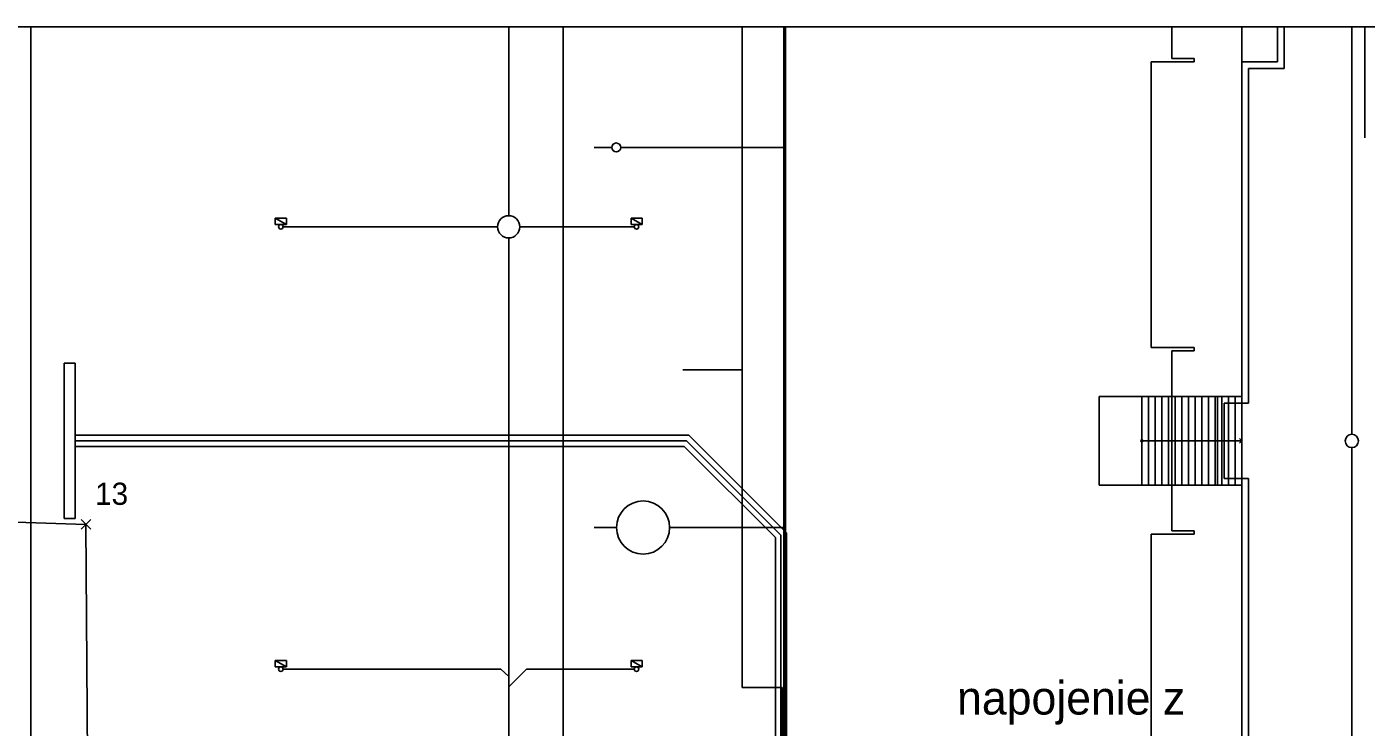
# Model space of a CAD drawing. Extents: x -263993 to -263783, y -1242294 to -1242146.
# Drawn here: x -263948.3 to -263888, y -1242177.3 to -1242145.8 of the extents above; entities that cross this region are included whole.
import ezdxf

# ---------------------------------------------------------------- set-up
doc = ezdxf.new("R2010")
doc.units = 0
for name, color, linetype in [('KFA_2D_SITUACIA_DSP', 7, 'Continuous'), ('KFA_ROZVODY_NN_BODY', 7, 'Continuous'), ('KFA_ROZVODY_NN_TRASA', 7, 'Continuous'), ('POPIS', 7, 'Continuous'), ('RAM_NA_TLAC_A3_1-500', 7, 'Continuous')]:
    doc.layers.add(name, color=color, linetype=linetype)

msp = doc.modelspace()

# ---------------------------------------------------------------- linework, layer by layer
at = {"layer": 'KFA_2D_SITUACIA_DSP'}
for p, q in [((-263948.093, -1242145.754), (-263948.093, -1242241.458)), ((-263926.593, -1242145.754), (-263926.593, -1242154.252)), ((-263926.593, -1242145.754), (-263926.593, -1242154.252)), ((-263924.143, -1242145.754), (-263924.143, -1242185.14)), ((-263916.093, -1242145.754), (-263916.093, -1242175.482)), ((-263914.218, -1242196.332), (-263914.218, -1242145.754)), ((-263914.143, -1242196.333), (-263914.143, -1242145.754)), ((-263896.768, -1242145.754), (-263896.768, -1242147.182)), ((-263893.618, -1242162.382), (-263893.618, -1242145.754)), ((-263892.018, -1242147.332), (-263892.018, -1242145.754)), ((-263892.018, -1242145.754), (-263892.018, -1242147.332)), ((-263891.718, -1242145.754), (-263891.718, -1242147.632)), ((-263888.673, -1242145.754), (-263888.673, -1242164.087)), ((-263895.768, -1242147.332), (-263897.693, -1242147.332)), ((-263897.693, -1242147.332), (-263897.693, -1242160.182)), ((-263896.768, -1242147.182), (-263895.768, -1242147.182)), ((-263895.768, -1242147.182), (-263895.768, -1242147.332)), ((-263893.618, -1242181.432), (-263893.618, -1242147.332)), ((-263893.618, -1242147.332), (-263892.018, -1242147.332)), ((-263892.018, -1242147.332), (-263893.618, -1242147.332)), ((-263893.618, -1242147.332), (-263893.618, -1242162.382)), ((-263891.718, -1242147.632), (-263893.318, -1242147.632)), ((-263893.318, -1242147.632), (-263893.318, -1242162.682)), ((-263921.957, -1242151.182), (-263922.757, -1242151.182)), ((-263917.093, -1242151.182), (-263921.557, -1242151.182)), ((-263914.143, -1242151.182), (-263917.093, -1242151.182)), ((-263937.093, -1242154.652), (-263937.093, -1242154.362)), ((-263937.093, -1242154.362), (-263936.593, -1242154.362)), ((-263936.593, -1242154.652), (-263937.093, -1242154.362)), ((-263936.593, -1242154.652), (-263937.093, -1242154.362)), ((-263937.093, -1242154.362), (-263937.093, -1242154.652)), ((-263936.593, -1242154.362), (-263936.593, -1242154.652)), ((-263921.093, -1242154.652), (-263921.093, -1242154.362)), ((-263921.093, -1242154.362), (-263920.593, -1242154.362)), ((-263920.593, -1242154.652), (-263921.093, -1242154.362)), ((-263920.593, -1242154.652), (-263921.093, -1242154.362)), ((-263921.093, -1242154.362), (-263921.093, -1242154.652)), ((-263920.593, -1242154.362), (-263920.593, -1242154.652)), ((-263936.593, -1242154.652), (-263937.093, -1242154.652)), ((-263937.093, -1242154.652), (-263936.593, -1242154.652)), ((-263936.743, -1242154.752), (-263927.093, -1242154.752)), ((-263920.944, -1242154.752), (-263926.093, -1242154.752)), ((-263920.593, -1242154.652), (-263921.093, -1242154.652)), ((-263921.093, -1242154.652), (-263920.593, -1242154.652)), ((-263926.593, -1242155.252), (-263926.593, -1242204.252)), ((-263897.693, -1242160.182), (-263895.768, -1242160.182)), ((-263895.768, -1242160.332), (-263896.768, -1242160.332)), ((-263896.768, -1242160.332), (-263896.768, -1242168.432)), ((-263895.768, -1242160.182), (-263895.768, -1242160.332)), ((-263946.093, -1242160.882), (-263946.593, -1242160.882)), ((-263946.593, -1242160.882), (-263946.593, -1242167.882)), ((-263946.093, -1242167.882), (-263946.093, -1242160.882)), ((-263916.093, -1242161.182), (-263918.763, -1242161.182)), ((-263900.043, -1242166.382), (-263900.043, -1242162.382)), ((-263900.043, -1242162.382), (-263893.618, -1242162.382)), ((-263898.118, -1242162.382), (-263898.118, -1242166.382)), ((-263897.818, -1242162.382), (-263897.818, -1242166.382)), ((-263897.518, -1242162.382), (-263897.518, -1242166.382)), ((-263897.218, -1242162.382), (-263897.218, -1242166.382)), ((-263896.918, -1242162.382), (-263896.918, -1242166.382)), ((-263896.618, -1242162.382), (-263896.618, -1242166.382)), ((-263896.318, -1242162.382), (-263896.318, -1242166.382)), ((-263896.018, -1242162.382), (-263896.018, -1242166.382)), ((-263895.718, -1242162.382), (-263895.718, -1242166.382)), ((-263895.418, -1242162.382), (-263895.418, -1242166.382)), ((-263895.118, -1242162.382), (-263895.118, -1242166.382)), ((-263894.818, -1242162.382), (-263894.818, -1242166.382)), ((-263893.618, -1242162.382), (-263894.718, -1242162.382)), ((-263894.718, -1242162.382), (-263894.718, -1242166.382)), ((-263894.518, -1242162.382), (-263894.518, -1242166.382)), ((-263894.218, -1242162.382), (-263894.218, -1242166.382)), ((-263893.918, -1242162.382), (-263893.918, -1242166.382)), ((-263893.618, -1242162.382), (-263893.618, -1242166.382)), ((-263893.318, -1242162.682), (-263894.418, -1242162.682)), ((-263894.418, -1242162.682), (-263894.418, -1242166.082)), ((-263918.489, -1242164.132), (-263946.093, -1242164.132)), ((-263918.489, -1242164.132), (-263914.1, -1242168.521)), ((-263918.593, -1242164.382), (-263946.093, -1242164.382)), ((-263918.696, -1242164.632), (-263946.093, -1242164.632)), ((-263918.696, -1242164.632), (-263914.6, -1242168.728)), ((-263918.593, -1242164.382), (-263914.35, -1242168.625)), ((-263898.118, -1242164.382), (-263893.618, -1242164.382)), ((-263893.618, -1242164.382), (-263893.721, -1242164.274)), ((-263893.618, -1242164.382), (-263893.721, -1242164.491)), ((-263888.673, -1242164.687), (-263888.673, -1242220.396)), ((-263893.618, -1242166.382), (-263900.043, -1242166.382)), ((-263894.718, -1242166.382), (-263893.618, -1242166.382)), ((-263894.418, -1242166.082), (-263893.318, -1242166.082)), ((-263893.618, -1242210.482), (-263893.618, -1242166.382)), ((-263893.618, -1242166.382), (-263893.618, -1242181.432)), ((-263893.318, -1242166.082), (-263893.318, -1242181.132)), ((-263946.593, -1242167.882), (-263946.093, -1242167.882)), ((-263922.745, -1242168.282), (-263921.745, -1242168.282)), ((-263914.143, -1242168.282), (-263919.355, -1242168.282)), ((-263896.768, -1242168.432), (-263895.768, -1242168.432)), ((-263895.768, -1242168.432), (-263895.768, -1242168.582)), ((-263914.6, -1242168.728), (-263914.6, -1242199.693)), ((-263914.35, -1242168.625), (-263914.35, -1242199.59)), ((-263914.1, -1242168.521), (-263914.1, -1242199.486)), ((-263895.768, -1242168.582), (-263897.693, -1242168.582)), ((-263897.693, -1242168.582), (-263897.693, -1242181.432)), ((-263937.093, -1242174.553), (-263937.093, -1242174.263)), ((-263937.093, -1242174.263), (-263936.593, -1242174.263)), ((-263936.593, -1242174.553), (-263937.093, -1242174.263)), ((-263936.593, -1242174.553), (-263937.093, -1242174.263)), ((-263937.093, -1242174.263), (-263937.093, -1242174.553)), ((-263936.593, -1242174.263), (-263936.593, -1242174.553)), ((-263921.093, -1242174.553), (-263921.093, -1242174.263)), ((-263921.093, -1242174.263), (-263920.593, -1242174.263)), ((-263920.593, -1242174.553), (-263921.093, -1242174.263)), ((-263920.593, -1242174.553), (-263921.093, -1242174.263)), ((-263921.093, -1242174.263), (-263921.093, -1242174.553)), ((-263920.593, -1242174.263), (-263920.593, -1242174.553)), ((-263936.593, -1242174.553), (-263937.093, -1242174.553)), ((-263937.093, -1242174.553), (-263936.593, -1242174.553)), ((-263936.743, -1242174.653), (-263926.953, -1242174.653)), ((-263926.953, -1242174.653), (-263926.593, -1242174.978)), ((-263925.798, -1242174.653), (-263926.593, -1242175.448)), ((-263920.944, -1242174.653), (-263925.798, -1242174.653)), ((-263920.593, -1242174.553), (-263921.093, -1242174.553)), ((-263921.093, -1242174.553), (-263920.593, -1242174.553)), ((-263916.093, -1242175.482), (-263914.293, -1242175.482)), ((-263914.293, -1242175.482), (-263914.293, -1242210.482))]:
    msp.add_line(p, q, dxfattribs=at)
for centre, radius in [((-263921.757, -1242151.182), 0.2), ((-263926.593, -1242154.752), 0.5), ((-263936.843, -1242154.752), 0.1), ((-263920.844, -1242154.752), 0.1), ((-263888.673, -1242164.387), 0.3), ((-263898.118, -1242164.382), 0.05), ((-263920.55, -1242168.282), 1.195), ((-263936.843, -1242174.653), 0.1), ((-263920.844, -1242174.653), 0.1)]:
    msp.add_circle(centre, radius, dxfattribs=at)
at = {"layer": 'KFA_ROZVODY_NN_BODY'}
for p, q in [((-263945.827, -1242168.361), (-263945.385, -1242167.919)), ((-263945.385, -1242168.361), (-263945.827, -1242167.919))]:
    msp.add_line(p, q, dxfattribs=at)
at = {"layer": 'KFA_ROZVODY_NN_TRASA'}
for p, q in [((-263949.218, -1242168.031), (-263945.606, -1242168.14)), ((-263945.606, -1242168.14), (-263945.443, -1242194.594))]:
    msp.add_line(p, q, dxfattribs=at)
at = {"layer": 'RAM_NA_TLAC_A3_1-500'}
msp.add_line((-263888.083, -1242145.754), (-263888.083, -1242150.754), dxfattribs=at)
msp.add_lwpolyline([(-263993.083, -1242145.754), (-263783.083, -1242145.754), (-263783.083, -1242294.254), (-263993.083, -1242294.254)], close=True, dxfattribs=at)

# ---------------------------------------------------------------- texts
at = {"layer": 'KFA_ROZVODY_NN_BODY'}
msp.add_text('13', height=1, dxfattribs=at).set_placement((-263945.198, -1242167.262))
at = {"layer": 'POPIS'}
msp.add_text('napojenie z', height=1.5, dxfattribs=at).set_placement((-263906.427, -1242176.695))

doc.saveas('drawing.dxf')
